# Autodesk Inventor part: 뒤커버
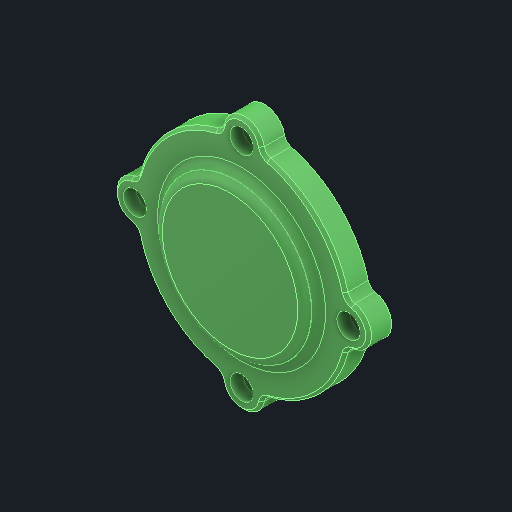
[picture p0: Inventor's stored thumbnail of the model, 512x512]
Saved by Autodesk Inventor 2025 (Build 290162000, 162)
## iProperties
Created: 2025-08
Part Number: 뒤커버
Material: 알루미늄 6061
Document SubType Name: Modeling
Designer: infra08
Density: 2.71 g/cm^3
Appearance: 기본값
Company: 한국ATC센터
Author: jhkim
Sending System: Autodesk Inventor 2026
Preprocessor: ST-DEVELOPER v20.1
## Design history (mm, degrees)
feature "솔리드1"
node "솔리드2"
